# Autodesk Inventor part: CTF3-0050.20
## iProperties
Shininess: 64.0
Length Units: 11269
Angle Units: 11279
Time Units: 11290
Mass Units: 11283
Length Display Precision: 3
Angle Display Precision: 2
Compacted: True
Part Number: CTF3-0050.20
Document SubType Name: Modeling
Created: 2004-01
Designer: Lollo
Density: 0.0
Volumn: 0.0
Area: 0.0
PropertySet Name: Model Information
Control State: 0
Master: False
Checked Out: False
Author: Lollo
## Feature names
1. Estrusione1 [Extrusion]
2. Foro1 [Hole]
3. Raccordo1 [Fillet]
4. Smusso1 [Chamfer]
5. Foro3 [Hole]
6. Raccordo3 [Fillet]
7. Smusso2 [Chamfer]
8. Smusso3 [Chamfer]
